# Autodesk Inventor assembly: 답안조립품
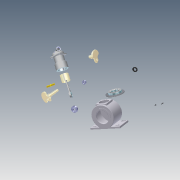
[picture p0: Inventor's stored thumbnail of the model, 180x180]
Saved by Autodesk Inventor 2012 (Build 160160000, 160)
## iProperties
Created: 2015-06
Part Number: 답안조립품
Document SubType Name: Assembly
Designer: User
Author: User
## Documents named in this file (15)
- C:\Documents and Settings\User\바탕 화면\450605V1016\답안조립품.iam
- C:\Documents and Settings\User\바탕 화면\450605V1016\본체.ipt
- C:\Documents and Settings\User\바탕 화면\450605V1016\메인 크랭크 축-구동부.ipt
- C:\Documents and Settings\User\바탕 화면\450605V1016\메인커버.ipt
- C:\Documents and Settings\User\바탕 화면\450605V1016\베어링 6204.ipt
- C:\Documents and Settings\User\바탕 화면\450605V1016\베어링 NA 4902.ipt
- C:\Documents and Settings\User\바탕 화면\450605V1016\실린더.ipt
- C:\Documents and Settings\User\바탕 화면\450605V1016\실린더헤드.ipt
- C:\Documents and Settings\User\바탕 화면\450605V1016\오일실.ipt
- C:\Documents and Settings\User\바탕 화면\450605V1016\커넥팅 로드.ipt
- C:\Documents and Settings\User\바탕 화면\450605V1016\크랭크 서브축.ipt
- C:\Documents and Settings\User\바탕 화면\450605V1016\피스톤.ipt
- C:\Documents and Settings\User\바탕 화면\450605V1016\피스톤 핀.ipt
- C:\Documents and Settings\User\바탕 화면\450605V1016\M4x0.7.ipt
- C:\Documents and Settings\User\바탕 화면\450605V1016\M5x0.8.ipt
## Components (4 placed, 4 different names)
1. 피스톤:1 — 각도:1
2. 피스톤 핀:1 — 각도:1
3. M4x0.7:1
4. M5x0.8:1
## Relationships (1: Angle 1)
- 각도:1 [Angle]: 피스톤:1 ↔ 피스톤 핀:1
